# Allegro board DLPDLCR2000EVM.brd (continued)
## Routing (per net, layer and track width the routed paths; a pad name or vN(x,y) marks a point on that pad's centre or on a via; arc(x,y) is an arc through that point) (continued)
R[4]: length 59.6
  LY2 w0.102: v3(30.66,36.24) 30.71,36.29 v1(30.71,36.73)
  LY3 w0.132: v2(29.49,27.94) 29.49,27.96 30.17,28.64 30.17,29.84 30.21,29.89 30.22,29.9 30.22,33.26 30.54,33.58 30.54,35.58 30.66,35.7 v3(30.66,36.24)
  BOTTOM w0.132: v2(29.49,27.94) 29.91,27.94 29.92,27.95 30.42,27.95 31.48,26.9 35.5,26.9 36.27,27.66 38.33,27.66 38.7,28.03 38.7,28.49 47.32,37.11 47.32,41.28 49.75,43.71 50.72,43.71 51.47,44.45 53.18,44.45 53.72,44.99 53.72,45.14 56.26,47.68 59.71,47.68 61.73,49.69 61.73,50.33 62.94,51.54 64.29,51.54 P1.46
R[5]: length 67.7
  TOP w0.132: v2(28.25,28.82) 30.24,30.8 30.24,35.41 30.71,35.88 U12.A12
  BOTTOM w0.132: P1.43 63.87,51.12 65.85,51.12 66.41,50.56 66.41,49.77 63.57,46.93 58.55,46.93 44.51,32.89 44.51,26.46 42.93,24.87 37.36,24.87 36.39,25.84 31.05,25.84 30.34,26.55 29.85,26.55 28.25,28.14 v2(28.25,28.82)
R[6]: length 55.3
  LY3 w0.102: 31.23,35.56 31.39,35.72 31.39,35.95 31.11,36.23 v4(31.11,37.13)
  LY3 w0.132: v2(31.62,27.62) 31.62,30.31 31.2,30.73 31.2,31.44 31.26,31.5 31.26,32.39 31.03,32.62 31.03,35.37 31.23,35.56
  BOTTOM w0.132: P1.44 61.35,51.14 61.35,49.78 59.58,48.01 55.69,48.01 53.83,46.15 52.1,46.15 50.27,44.32 49.89,44.32 46.95,41.38 46.95,37.26 38.32,28.64 36.5,28.64 35.1,27.23 32.01,27.23 31.62,27.62 v2(31.62,27.62)
R[7]: length 50.9
  LY2 w0.102: v1(31.11,36.73) v3(31.11,35.84)
  LY3 w0.102: v3(31.11,35.84) 31.11,35.8 30.87,35.56
  LY3 w0.132: 30.87,35.56 30.79,35.48 30.79,33.48 30.46,33.15 30.46,29.8 30.45,29.79 30.45,28.52 v2(30.93,28.04)
  BOTTOM w0.132: v2(30.93,28.04) 35.08,28.04 36.24,29.19 38.41,29.19 46.47,37.25 46.47,42.56 50.43,46.52 53.72,46.52 55.74,48.54 58.76,48.54 P1.41
RED_CATHODE: length 12.2
  LY3 w0.254: 60.48,19.09 61.01,19.61 63.8,19.61 64.18,19.98 v4(64.45,19.98)
  LY3 w0.508: 60.48,19.09 54.32,19.09 TP29.1
  vias: v2(40.64,17.83) v2(41.2,17.83) v2(41.73,17.83)
REF_VRST: length 5.7
  LY2 w0.102: v1(66.45,19.58) v3(66.45,19.23)
  LY3 w0.132: v4(70.22,17.01) 67.52,17.01 66.45,18.08 v3(66.45,19.23)
RESETZ: length 80.1
  TOP w0.132: v2(24.58,27.89) 24.58,25.09 23.6,24.1 23.6,19.87 24.49,18.97 35.05,18.97 36.98,20.9 36.98,22.33 37.34,22.68 50.5,22.68 TP24.1 52.98,25.16 55.92,25.16 56.76,26 v2(57.6,26)
  LY2 w0.102: v3(29.1,39.46) 29.16,39.53 v1(29.91,39.53) ; v3(66.58,21.1) 66.45,20.97 v1(66.45,20.78)
  LY3 w0.102: 28.81,39.52 28.78,39.52
  LY3 w0.132: v2(57.6,26) 58.03,25.58 67.41,25.58 68.38,24.61 68.85,24.61 69.19,24.27 69.19,23.19 68.86,22.86 67.43,22.86 66.58,22.01 v3(66.58,21.1) ; 28.81,39.52 28.87,39.46 v3(29.1,39.46) ; 28.78,39.52 28.06,39.52 27.88,39.34 27.1,39.34 26,38.24 26,37.71 24.89,36.6 24.89,33.02 25.3,32.61 25.3,28.61 v2(24.58,27.89)
RLIM: length 2.6
  TOP w0.203: U5.F5 U5.F6 U5.F7 64.85,19.05 64.54,18.75 64.54,18.16 R92.1
RTSZ: length 2.6
  LY2 w0.102: 64.03,19.61 64.08,19.66 64.08,20.03 64.44,20.38 v1(64.85,20.38)
  LY2 w0.132: 64.03,19.61 63.54,19.11 v1(62.99,19.11)
S_STAT_LED: length 2
  TOP w0.132: v2(33.72,6.95) D2.1
  BOTTOM w0.132: R129.1 v2(33.72,6.95)
S_STAT_LEDDRV: length 21.3
  TOP w0.132: U8.4 v2(52.58,9)
  LY3 w0.132: v2(35.31,8.76) 39.75,8.76 40.51,8 44.88,8 45.59,7.29 50.87,7.29 v2(52.58,9)
  BOTTOM w0.132: v2(35.31,8.76) 35.29,8.78 R129.2
SBPWR_FB: length 2.5
  TOP w0.132: R94.2 R95.1 45.83,11.13 45.58,10.87 U7.1
SBPWR_IN: length 2.8
  TOP w0.132: U7.4 48.3,9.05 v2(48.31,9.04)
  BOTTOM w0.132: R128.1 C133.1 47.73,9.04 v2(48.31,9.04)
SCL: length 40.8
  TOP w0.132: v2(30.08,27.56) 30.08,29.51 30.93,30.35 30.93,31.54 31.32,31.93 31.32,34.64 31.03,34.93 31.03,35.26 31.51,35.73 U12.A10 ; U4.6 v2(27.62,19.93)
  LY3 w0.132: v2(30.08,27.56) 30.08,22.39 v2(27.62,19.93) 30.13,17.41 30.13,14.94 31.24,13.83 31.24,3.1 P2.19
  BOTTOM w0.132: R119.1 27.61,20.92 27.61,19.94 v2(27.62,19.93)
SDA: length 38.5
  TOP w0.132: v2(28.91,19.93) 28.89,19.94 U4.5
  LY3 w0.132: P2.20 32.44,13.6 30.83,15.2 30.83,18 v2(28.91,19.93) 30.93,21.95 30.93,25.85 32.1,27.02 32.1,30.16 32.46,30.52 32.46,32.94 31.83,33.57 31.83,36.13 31.51,36.45 v4(31.51,37.13)
  BOTTOM w0.132: R118.1 28.91,20.92 v2(28.91,19.93)
SEL_A0: length 9.2
  TOP w0.132: U4.1 v2(25.08,14.95)
  LY3 w0.132: J5.2 25.08,10.34 v2(25.08,14.95)
  BOTTOM w0.132: R123.1 25.07,15.84 25.07,14.96 v2(25.08,14.95)
SEL_A1: length 15.1
  TOP w0.132: U4.2 26.35,14.96 v2(26.37,14.95)
  LY3 w0.132: J4.2 25.31,7.26 27.05,7.26 28.06,8.27 28.06,12.19 26.37,13.89 v2(26.37,14.95)
  BOTTOM w0.132: v2(26.37,14.95) 26.37,15.84 R122.1
SEL_A2: length 2.4
  TOP w0.132: v2(27.66,14.95) 27.66,15 27.62,15.04 U4.3
  BOTTOM w0.132: R121.1 27.62,14.99 v2(27.66,14.95)
SENS1: length 5.8
  LY3 w0.132: v4(65.25,20.38) 65.01,20.62 64.16,20.62 64.01,20.78 62.26,20.78 62.14,20.89 60.92,20.89 60.37,20.34 v2(59.84,20.34)
SENS2: length 4.3
  TOP w0.203: R91.2 v4(62.99,18.16)
  LY3 w0.132: v4(62.99,18.16) 63.93,18.16 64.8,19.02 64.8,19.53 v4(65.25,19.98)
SPICLK: length 85.2
  TOP w0.132: v2(36.24,32.07) 35.75,32.56 35.53,32.56 R78.1 ; U3.6 55.94,27.05 v2(55.94,27.04)
  LY3 w0.132: v4(66.05,20.78) 65.7,21.13 64.41,21.13 63.68,21.87 59.65,21.87 59.41,21.63 55.62,21.63 54.23,23.01 52.53,23.01 51.89,22.38 36.54,22.38 35.97,22.95 35.97,25.96 37.01,27 37.01,30.88 36.24,31.65 v2(36.24,32.07) 37.81,32.07 38.41,31.47 62.48,31.47 62.74,31.22 62.74,27.53 62.33,27.13 61.29,27.13 61.09,27.33 61.09,28.47 60.93,28.63 60.46,28.63 60.33,28.49 60.33,27.44 59.92,27.04 v2(55.94,27.04)
  BOTTOM w0.132: v2(55.94,27.04) 55.07,27.04 R111.2
SPICSZ0: length 19.6
  TOP w0.132: v2(49.25,29.58) 49.24,29.59 U3.1 46.28,29.59 45.25,30.62 38.57,30.62 37.65,29.7 35.04,29.7 34.77,29.97 34.77,31.8 34.84,31.86 34.84,32.31 R76.1
  BOTTOM w0.132: R104.2 48.08,29.58 v2(49.25,29.58)
SPICSZ1: length 48.4
  TOP w0.132: v2(58.65,26.07) 58.3,26.42 52.12,26.42 50.51,24.81 40.34,24.81 39.24,25.91 39.24,25.91 39.24,27.97 38.58,28.64 34.91,28.64 34.16,29.39 R75.1
  LY3 w0.102: 67.23,21.25 66.81,20.83 66.49,20.83 66.05,20.38 v4(66.05,20.38)
  LY3 w0.132: v2(58.65,26.07) 67.86,26.07 68.4,25.53 68.79,25.53 69.75,24.57 69.75,22.4 69.03,21.69 67.68,21.69 67.23,21.25
  BOTTOM w0.132: v2(58.65,26.07) 58.8,26.21 R110.2
SPIMISO: length 70.4
  TOP w0.132: v2(46.08,28.32) U3.2
  LY2 w0.102: v1(66.05,19.58) 66.05,18.95 v3(65.92,18.83) ; v1(33.91,36.73) 34.1,36.54 v3(34.1,35.99)
  LY3 w0.102: 65.92,18.81 v3(65.92,18.83)
  LY3 w0.132: 65.92,18.81 65.92,17.99 63.48,15.55 v2(62.75,15.55) ; v2(54.66,21.02) 54.16,21.51 52.15,21.51 51.99,21.67 35.65,21.67 35.01,22.31 35.01,23.09 34.67,23.43 34.67,27.69 36.22,29.24 36.22,29.66 34.81,31.08 34.81,33.22 34.23,33.79 34.23,35.43 34.1,35.56 v3(34.1,35.99)
  BOTTOM w0.132: R112.2 v2(46.08,28.32) 46.08,25.53 46.84,24.77 49.48,24.77 50.06,24.18 50.06,23.67 50.44,23.29 53.59,23.29 54.66,22.23 v2(54.66,21.02) 54.66,19.04 58.15,15.55 v2(62.75,15.55)
SPIMOSI: length 98.1
  TOP w0.132: R77.1 v4(37.5,30.21) ; U3.5 v2(52.88,25.78)
  LY3 w0.132: v4(66.05,19.98) 66.05,19.84 66.27,19.61 69.82,19.61 70.57,20.37 70.57,25.73 69.58,26.72 56.97,26.72 56.63,26.38 52.8,26.38 51.93,27.25 51.93,29.7 50.72,30.91 37.72,30.91 37.5,30.7 v4(37.5,30.21) 38.77,30.21 39.22,29.77 39.22,23.8 39.57,23.44 45.22,23.44 45.41,23.63 45.41,23.84 45.22,24.03 40.34,24.03 40.16,24.22 40.16,24.43 40.34,24.61 45.22,24.61 45.41,24.8 45.41,27.09 45.59,27.28 45.86,27.28 46.05,27.09 46.05,24.22 46.23,24.03 46.5,24.03 46.69,24.22 46.69,27.09 46.87,27.28 47.14,27.28 47.33,27.09 47.33,24.39 47.69,24.03 48.16,24.03 48.35,24.22 48.35,24.7 48.54,24.89 48.8,24.89 48.99,24.7 48.99,24.22 49.18,24.03 49.89,24.03 51.64,25.78 v2(52.88,25.78)
STAT_DRV: length 3.6
  TOP w0.132: U6.4 38.69,10.56 v2(38.35,10.9)
  BOTTOM w0.132: R126.2 38.34,10.91 v2(38.35,10.9)
STAT_LED: length 1.9
  TOP w0.132: v2(36.89,12.71) D3.2
  BOTTOM w0.132: R126.1 v2(36.89,12.71)
SWN: length 3.4
  TOP w0.203: D1.1 69.63,19.85 69.55,19.94 L4.2 68.46,19.98 U5.A5
SWP: length 2.7
  TOP w0.203: L4.1 68.49,17.67 67.68,17.67 67.59,17.75 67.59,18.24 66.85,18.98 U5.A7
SYSPWR: length 65.2
  TOP w0.203: U5.A4 67.1,20.38 67.23,20.51 67.23,20.52 67.69,20.97 v2(67.69,21.12) ; U5.A2 U5.A1 66.86,21.58 67.26,21.99 68.09,21.99 C41.1
  TOP w0.381: 12.7,10.92 J2.1 ; J2.1 11.51,13.51 ; J2.1 12.7,16.1 ; J2.1 13.89,13.51 ; J3.1 17.7,13.51 ; J3.1 15.32,13.51 ; J3.1 16.51,14.71 ; J3.1 16.51,12.32 ; C29.1 v2(68.69,26.1) ; C30.1 68.86,24.83 v2(68.69,25.01) ; U1.1 10.43,44.95 10.31,44.83 9.53,44.83 v2(9.53,45.54) ; v2(27.56,26.56) C23.2 28.35,25.84 28.46,25.96 U2.1 ; v2(68.53,22.38) 68.3,22.15 C41.1 ; v2(55.4,7.87) 55.64,7.63 R96.2 ; C31.1 68.92,23.56 v2(68.69,23.33) ; R97.2 v2(67.31,10.93) ; C28.1 v2(68.69,27.37)
  LY3 w0.381: v5(21.4,14.02) 22.32,14.94 22.32,21.31 v2(27.56,26.56)
  LY4 w0.381: J3.1 17.4,12.62 ; J3.1 15.62,14.41 ; J3.1 17.4,14.41 ; J3.1 15.62,12.62 ; J2.1 13.89,10.92 ; J2.1 11.51,16.1 ; J2.1 13.89,16.1 ; J2.1 11.51,10.92
  BOTTOM w0.381: R124.1 J2.1 ; v2(54.76,8.84) 54.94,9.02 R125.2 ; v2(60.73,19.98) 61.49,19.98 61.58,20.07 R117.1 ; R128.2 45.73,7.94 v2(45.72,7.92) ; v2(68.53,22.38) 68.3,22.15 C41.1
  vias: v2(65.79,45.33) v2(65.79,44.06) v2(65.79,42.79) v2(65.79,41.52) v2(65.79,40.25) v2(65.79,38.98) v2(65.79,37.71) v2(65.79,36.44) v2(65.79,35.17) v2(65.79,33.9) v2(65.79,32.63) v2(66.61,45.33) v2(66.61,44.06) v2(66.61,42.79) v2(66.61,41.52) v2(66.61,40.25) v2(66.61,38.98) v2(66.61,37.71) v2(66.61,36.44) v2(66.61,35.17) v2(66.61,33.9) v2(66.61,32.63) v5(19.05,14.02) v5(19.05,13.32) v5(19.81,14.02) v5(19.81,13.32) v5(20.57,14.02) v5(20.57,13.32) v5(21.4,13.32)
SYSPWR_SHUNT: length 2.4
  BOTTOM w0.381: J2.3 9.69,8.83 R124.2
THERMISTOR_P: length 4.1
  TOP w0.132: TP33.1 61.84,16.31 61.95,16.42 R91.1 R89.1 RT1.1
TSTPT_0: length 17.7
  TOP w0.132: TP25.1 34.8,22 v4(35.46,22.66)
  LY2 w0.102: v1(33.11,36.73) 33.11,36.15 33.23,36.03 33.23,35.68 33.35,35.56
  LY2 w0.132: 33.35,35.56 v3(34.69,34.21)
  LY3 w0.132: v4(35.46,22.66) 35.26,22.86 35.26,23.19 34.92,23.53 34.92,27.5 36.47,29.05 36.47,29.95 35.05,31.37 35.05,33.43 34.69,33.78 v3(34.69,34.21)
TSTPT_1: length 18.4
  TOP w0.132: U12.A8 32.31,34.96 32.21,34.86 32.21,34.53 32.31,34.43 32.31,31.96 31.99,31.64 31.99,30.02 31.94,29.98 31.94,29.94 30.5,28.5 30.5,27.36 30.3,27.16 29.92,27.16 29.6,27.48 27.36,27.48 26.86,26.98 26.66,26.78 26.66,25.93 25.08,24.35 24.6,24.35 TP21.1
TSTPT_2: length 12.5
  TOP w0.132: TP19.1 38.25,29.36 v4(35.93,29.36)
  LY3 w0.102: v4(32.71,37.13) 32.71,36.83 33.54,36 33.54,35.56
  LY3 w0.132: 33.54,35.56 33.54,35.37 33.74,35.17 33.74,33.51 34.21,33.05 34.21,31.08 v4(35.93,29.36)
TSTPT_3: length 18.3
  TOP w0.132: v4(35.71,22.02) 35.71,21.82 TP27.1
  LY2 w0.102: 33.98,35.56 33.51,36.03 v1(33.51,36.73)
  LY2 w0.132: 33.98,35.56 34.54,34.99 v3(34.81,34.99)
  LY3 w0.132: v4(35.71,22.02) 35.71,22.49 35.75,22.53 35.75,22.78 35.59,22.95 35.59,23.22 35.16,23.64 35.16,27.38 36.72,28.93 36.72,30.26 35.84,31.14 35.84,33.83 34.81,34.86 v3(34.81,34.99)
TSTPT_4: length 19.2
  TOP w0.132: U12.A7 32.71,35.2 33.53,34.37 33.53,33.84 33.34,33.66 33.34,32.05 33.09,31.8 32.76,31.8 32.36,31.4 32.36,29.47 32.02,29.13 32.02,27.47 31.78,27.23 30.85,27.23 30.45,26.83 29.77,26.83 29.45,27.14 27.5,27.14 27,26.64 27,25.79 TP22.1
TSTPT_5: length 19.6
  TOP w0.132: TP20.1 44.22,29.97 44.08,30.11 40.19,30.11 39.05,28.97 35.27,28.97 v4(34.74,29.5)
  LY3 w0.102: v4(32.31,37.13) 32.31,36.95 33.25,36.01 33.25,35.56
  LY3 w0.132: 33.25,35.56 33.25,35.31 33.49,35.06 33.49,33.41 33.96,32.95 33.96,30.28 v4(34.74,29.5)
TSTPT_6: length 4.9
  TOP w0.132: TP6.1 v4(31.88,45.16)
  LY3 w0.102: v4(31.91,41.13) 31.91,41.92 31.76,42.07 31.76,42.3 31.91,42.45 31.91,42.67
  LY3 w0.132: 31.91,42.67 31.91,45.13 v4(31.88,45.16)
TSTPT_7: length 4.3
  TOP w0.132: TP3.1 31.52,45.24 31.52,43.38 31.91,43 U12.R9
VBIAS: length 75.9
  TOP w0.203: v2(68.27,16.23) 67.93,16.56 67.74,16.56 66.92,17.38 C40.1 66.92,18.31 66.45,18.78 U5.B7
  TOP w0.381: R68.1 v2(13.98,33.26)
  BOTTOM w0.381: v2(68.27,16.23) 66.89,16.23 66.54,16.58 64.86,16.58 64.24,15.96 64.24,15.31 63.43,14.5 51.77,14.5 51.23,15.04 38.53,15.04 30.89,22.68 30.89,23.46 28.48,25.86 27.7,25.86 27.64,25.93 27.37,25.93 26.98,26.31 23.32,26.31 21.21,24.21 14.25,24.21 13.13,25.32 13.13,32.41 v2(13.98,33.26)
VOFS: length 57.8
  TOP w0.152: 65.49,17.32 65.49,15.4
  TOP w0.203: U5.C7 66.05,17.81 C39.1 65.9,17.73 65.49,17.32 ; 65.49,15.4 v2(66.23,14.66)
  TOP w0.381: R107.1 v2(23.93,25.1)
  BOTTOM w0.381: v2(23.93,25.1) 25.91,25.1 27.57,23.43 29.26,23.43 29.72,22.97 29.72,21.92 37.97,13.67 50.43,13.67 50.83,13.27 64.84,13.27 v2(66.23,14.66)
VRST: length 71.9
  TOP w0.203: v2(71.01,18.05) R93.1 D1.2 71.07,19.01 C42.1
  TOP w0.381: v2(14.17,23.34) 13.36,24.16 R69.1
  BOTTOM w0.381: v2(14.17,23.34) 21.29,23.34 23.65,25.7 26.51,25.7 26.93,25.28 28.23,25.28 30.3,23.21 30.3,22.3 38.23,14.38 50.86,14.38 51.35,13.89 63.84,13.89 65.24,15.3 68.27,15.3 v2(71.01,18.05)
VSYNC: length 36.3
  LY2 w0.102: v1(29.91,39.13) 29.68,39.13 29.53,38.98 28.73,38.98
  LY2 w0.132: v3(28.56,38.98) 28.73,38.98
  LY3 w0.132: v3(28.56,38.98) 26.46,36.88 26.46,36.7 25.41,35.65 25.41,34.71 25.96,34.16 26.04,34.16 26.04,34.15 v2(26.03,34.15)
  BOTTOM w0.132: v2(26.03,34.15) 26.04,34.15 26.04,34.16 26.09,34.16 26.17,34.08 26.36,34.08 27.05,34.77 28.81,34.77 29.61,33.96 34.08,33.96 39.67,39.56 39.67,47.12 42.6,50.04 P1.27
X_OUT1: length 1.7
  BOTTOM w0.132: C122.1 R102.2 21.93,37.63 XD100.1
N16791220: length 3.6
  TOP w0.381: R96.1 57.66,8.48 58.04,8.86 59.13,8.86 59.41,9.14 U10.5
N16866908: length 2.5
  TOP w0.132: U4.7 v2(26.35,19.93)
  BOTTOM w0.132: v2(26.35,19.93) R120.1

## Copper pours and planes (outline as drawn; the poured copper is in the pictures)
DGND on TOP: 71.37,31.8 71.37,46.02 69.41,46.02 69.15,45.77 69.15,32.12 69.47,31.8
DGND on TOP: 61.02,31.8 61.02,46.02 62.99,46.02 63.25,45.77 63.25,32.12 62.93,31.8
DGND on BOTTOM: 29.06,41.63 30.86,41.63 30.87,41.64 31.57,41.64 31.65,41.72 31.65,43.99 31.01,44.63 25.78,44.63 25.59,44.44 25.59,44.18 26.82,42.95 28.3,42.95 28.96,42.29 28.96,41.73
DGND on BOTTOM: 34.93,40.64 34.93,37.13 34.65,36.86 33.32,36.86 33.12,37.06 33.12,40.01 33.05,40.08 32.72,40.08 32.11,39.47 32.11,38.94 32.49,38.56 32.49,37.64 31.85,37.01 31.85,36.12 31.95,36.02 34.75,36.02 36.32,37.59 36.32,45.72 36.11,45.93 33.92,45.93 33.71,45.72 33.71,41.86
DGND on LY2, LY5: 0.76,53.85 63.5,53.85 71.94,50.35 75.44,41.91 75.44,12.7 71.94,4.26 63.5,0.76 3.05,0.76 3.05,19.11 12.76,19.11 12.76,40.55 0.76,40.55
VINTF on BOTTOM: 30.68,35 30.68,36.98 31.22,37.52 31.22,37.9 31.95,38.63 32.26,38.63 32.38,38.51 32.38,37.8 31.67,37.08 31.67,34.98 31.52,34.82 30.86,34.82
VINTF on LY4: 16.74,0.79 16.74,10.31 10.26,10.31 10.26,16.79 33.3,16.79 33.3,13.54 38.35,13.54 38.35,12.52 52.63,12.52 52.63,10.36 56.21,10.36 56.21,7.95 62.36,7.95 62.36,12.75 55.68,12.75 55.68,19.08 34.19,19.08 34.19,23.19 29.85,23.19 29.85,34.11 32.87,34.11 32.87,38.99 27.13,38.99 27.13,33.68 25.86,33.68 25.86,23.19 12.78,23.19 12.78,19.1 3.07,19.1 3.07,0.79
BLU_CATHODE on TOP: 39.29,21.21 45.16,21.21 49.23,17.14 53.59,17.14 53.75,16.99 53.75,16.03 53.59,15.88 48.84,15.88 44.27,20.45 39.29,20.45
GRN_CATHODE on TOP: 39.32,20.22 41.91,20.22 41.96,20.17 41.96,19.51 41.91,19.46 39.32,19.46
GRN_CATHODE on LY3: 40.31,20.17 40.36,20.22 48.59,20.22 49.76,19.05 53.47,19.05 53.67,18.85 53.67,17.98 53.49,17.81 49.45,17.81 47.8,19.46 40.36,19.46 40.31,19.51
L1 on TOP: 66.34,21.53 66.34,22.34 66.66,22.66 66.66,25.91 66.92,26.16 68.25,26.16 68.25,22.54 67.56,21.86 66.62,21.86 66.55,21.78 66.55,21.53
L2 on TOP: 65.56,21.48 65.56,21.83 64.95,22.44 64.95,26 65.1,26.15 66.22,26.15 66.45,25.92 66.45,22.85 66.12,22.52 66.12,22.06 65.76,21.7 65.76,21.5 65.74,21.48
LED_ANODE on TOP: 51.61,21.59 51.61,22.36 52.11,22.85 53.77,22.85 56.56,25.64 62.63,25.64 63.6,24.67 63.6,22.54 63.75,22.39 63.75,22.03 64.16,21.63 64.16,20.74 64.11,20.69 62.35,20.69 62.12,20.92 62.12,23.99 61.71,24.4 56.68,24.4 53.87,21.59
LED_ANODE on TOP: 39.73,17.2 38.51,17.2 38.4,17.3 38.4,21.36 38.63,21.59 52.25,21.59 52.25,22.38 37.74,22.38 37.44,22.07 37.44,16.59 37.57,16.46 39.73,16.46
P1P0V on TOP: 17.09,47.02 17.09,42.95 17.27,42.77 20.17,42.77 20.57,43.18 20.57,46.76 20.09,47.24 17.32,47.24
P1P0V on BOTTOM: 27.76,41.27 24.36,41.27 23.34,42.29 17.88,42.29 17.32,42.85 17.32,45.03 18.03,45.75 24.92,45.75 25.35,45.31 25.35,43.89 26.53,42.71 28.28,42.71 28.75,42.24 28.75,41.53 28.91,41.38 31.65,41.38 31.65,39.98 31.57,39.9 31.14,39.9 31.04,40.01 31.04,40.23 30.96,40.31 28.73,40.31
P1P0V_SW on TOP: 16.21,44.2 13.36,44.2 13.16,44.4 13.16,45.52 13.33,45.69 16.21,45.69
P1P8V on TOP: 35.13,28.03 35.13,23.96 35.31,23.79 38.2,23.79 38.61,24.19 38.61,24.2 38.99,24.58 38.99,27.97 38.45,28.5 35.73,28.5 35.48,28.26 35.36,28.26
P1P8V on BOTTOM: 33.3,40.26 32.64,40.26 32.05,39.67 31.9,39.67 31.8,39.78 31.8,40.28 32.44,40.92 34.32,40.92 34.72,40.51 34.72,37.14 34.62,37.03 33.43,37.03 33.3,37.16
P1P8V on LY4: 0.84,43.92 12.73,43.92 12.73,48.62 60.15,48.62 60.15,19.33 68.43,19.33 68.43,20.95 70.26,20.95 70.26,15.06 66.34,15.06 66.34,7.98 62.76,7.98 62.76,13.16 56.08,13.16 56.08,19.48 34.65,19.48 34.65,23.62 30.28,23.62 30.28,33.71 33.27,33.71 33.27,39.4 26.75,39.4 26.75,34.09 25.45,34.09 25.45,23.6 12.78,23.6 12.78,40.56 0.84,40.56
P1P8V_SW on TOP: 34.24,25.21 31.39,25.21 31.19,25.41 31.19,26.53 31.37,26.71 34.24,26.71
P2P5V on TOP: 46.6,10.24 46.6,12.04 46.72,12.17 47.94,12.17 48.02,12.09 48.02,10.26 47.92,10.16 46.67,10.16
P2P5V on LY4: 33.3,13.13 37.95,13.13 37.95,12.12 52.22,12.12 52.22,10.36 48.01,10.36 48.01,8.97 33.3,8.97
RED_CATHODE on TOP: 39.32,18.21 41.91,18.21 41.96,18.16 41.96,17.5 41.91,17.45 39.32,17.45
RED_CATHODE on BOTTOM: 40.39,18.21 46.63,18.21 49.38,20.95 53.59,20.95 53.75,20.8 53.75,19.84 53.59,19.68 49.61,19.68 47.37,17.45 40.39,17.45 40.34,17.5 40.34,18.16
RLIM on TOP: 63.69,17.54 63.69,18.72 63.91,18.95 64.67,18.95 64.75,18.88 64.75,18.82 64.6,18.67 64.6,17.63 64.41,17.45 63.78,17.45
SWN on TOP: 66.97,20.08 67.21,20.08 67.83,20.7 70.33,20.7 70.54,20.49 70.54,19.54 70.42,19.42 69.74,19.42 69.48,19.16 67.89,19.16 67.17,19.89 66.97,19.89
SWP on TOP: 67.13,18.83 68.94,18.83 69.11,18.66 69.11,17.5 69.01,17.41 67.69,17.41 67.49,17.6 67.49,18.2 67.13,18.55
SYSPWR on TOP: 63.88,46.09 68.52,46.09 68.52,31.8 63.88,31.8
SYSPWR on TOP: 14.99,11.29 22.1,11.29 22.35,11.54 22.35,15.8 22.1,16.05 18.8,16.05 18.61,15.86 14.61,15.86 13.84,16.62 11.18,16.62 10.67,16.12 10.67,10.66 11.11,10.21 13.91,10.21
SYSPWR on LY4: 17.18,0.76 17.18,10.72 10.67,10.72 10.67,16.38 32.89,16.38 32.89,8.56 48.41,8.56 48.41,9.96 55.8,9.96 55.8,7.56 66.78,7.56 66.78,14.66 70.66,14.66 70.66,21.36 68.02,21.36 68.02,19.66 60.58,19.66 60.58,49.02 12.32,49.02 12.32,44.32 0.81,44.32 0.81,53.85 63.12,53.85 63.7,53.85 64.54,53.8 65.48,53.67 66.34,53.49 67.26,53.24 68.35,52.81 69.37,52.27 70.41,51.61 71.3,50.9 71.88,50.34 72.39,49.83 73.2,48.79 73.94,47.65 74.6,46.2 74.9,45.36 75.21,44.07 75.39,42.8 75.41,41.91 75.41,12.06 75.36,11.56 75.23,10.64 74.9,9.27 74.3,7.65 73.46,6.17 72.72,5.16 71.91,4.27 70.87,3.35 69.77,2.57 68.76,2.01 67.56,1.5 65.99,1.04 65.28,0.91 64.39,0.81 64.19,0.8 63.7,0.79 63.47,0.79
VRST on TOP: 69.97,19.15 71.38,19.15 71.41,19.12 71.41,18.12 71.1,17.8 70.13,17.8 69.97,17.96

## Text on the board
BOTTOM: LAYER 6 - SECONDARY SIDE | 6
Board Geometry/Soldermask Bottom: SOLDERMASK - SECONDARY SIDE | 8
Ref Des/Silkscreen Bottom: CCA 2515211 | ESD 2515209 | PCB 2515210 | TEXAS INSTRUMENTS | FOR EVALUATION ONLY : NOT FCC APPROVED FOR RESALE | SILKSCREEN - SECONDARY SIDE | 10
TOP: LAYER 1 - PRIMARY SIDE | 1
Board Geometry/Soldermask Top: SOLDERMASK - PRIMARY SIDE | 7
Ref Des/Silkscreen Top: DLP003 | DLPDLCR2000EVM | SILKSCREEN - PRIMARY SIDE | 9 | Pb
LY2: LAYER 2 - GND PLANE | 2
LY3: LAYER 3 - SIGNAL | 3
LY4: LAYER 4 - PWR PLANE | 4
LY5: LAYER 5 - GND PLANE | 5
DIMENSION: 2 PLCS | SOLDERPASTE - PRIMARY SIDE | 13 | 11 | DRILL DRAWING | 10. MICRO VIAS TO BE FILLED AND PLANARIZED PRIOR | TO PLATING, VENDOR TO DETERMINE METHOD. | 9. VIAS CAN CONFORM TO CLASS 2 REQUIREMENTS AND | SHOULD BE TEARDROPPED BY FAB VENDOR. | LAYER STACK: | LAYER 1 - TOP SIDE, 3/8oz Cu START | LAYER 2 - GND PLANE, 3/8oz Cu | LAYER 3 - SIGNAL, 1/2oz Cu | LAYER 4 - PWR PLANE, 1/2oz Cu | LAYER 5 - GND PLANE, 3/8oz Cu | LAYER 6 - BOTTOM SIDE, 3/8oz Cu START | 50 OHMS SE - 0.0052 | 100 OHMS DIFF 0.004 WIDTH/0.007 SPACE
DISPLAY_TOP: SOLDERPASTE - SECONDARY SIDE | 12
User.11: 19 | TOP SIDE VIA PLUG
User.25: 59 | 1 | 60 | 2 | 25 | 15 | 26 | 14 | 12 | 13 | *
User.27: 1 | 119 | 59 | 61 | 2 | 62 | 60 | 120 | TM
User.28: 13 | DLPDLCR2000EVM | 2515210 | E1 | TEXAS INSTRUMENTS
User.44: 3. | 2. | 4. | 1. | to be placed close to the memory pins. | See set of resistors that needs to be placed close to | See DLPC2607 datasheet for PCB design considerations, | All resistors in this page should be placed mid-way | between DLPC and memory, unless noted otherwise. | DLPC. See resistor connecting to CK and CK\ that needs | length matching, etc. | XDPP and their passives should be placed very close | See DLPC2607 datasheet for all supported mDDR SDRAM | to their DLPC pins. | memories, their size, speed grade, etc. | Design Notes:
User.45: FIGURE | SIZE | 8.0 | 9.0 | 10.0 | 12.0 | 24.0 | 40.0 | 125.0 | 120.0x40.0 | 140.0x40.0 | DRILL CHART: TOP to BOTTOM | ALL UNITS ARE IN MILS | TOLERANCE | +0.0/-8.0 | +0.0/-0.0 | +0.0/-10.0 | +3.0/-12.0 | +3.0/-3.0 | PLATED | NON-PLATED | QTY | 306 | 12 | 17 | 10 | 2 | 3 | 95 | 5 | 1 | 4.0 | DRILL CHART: TOP to LY3 | DRILL CHART: LY2 to LY3 | DRILL CHART: TOP to LY2 | +0.0/-4.0 | 213 | 48 | 61
